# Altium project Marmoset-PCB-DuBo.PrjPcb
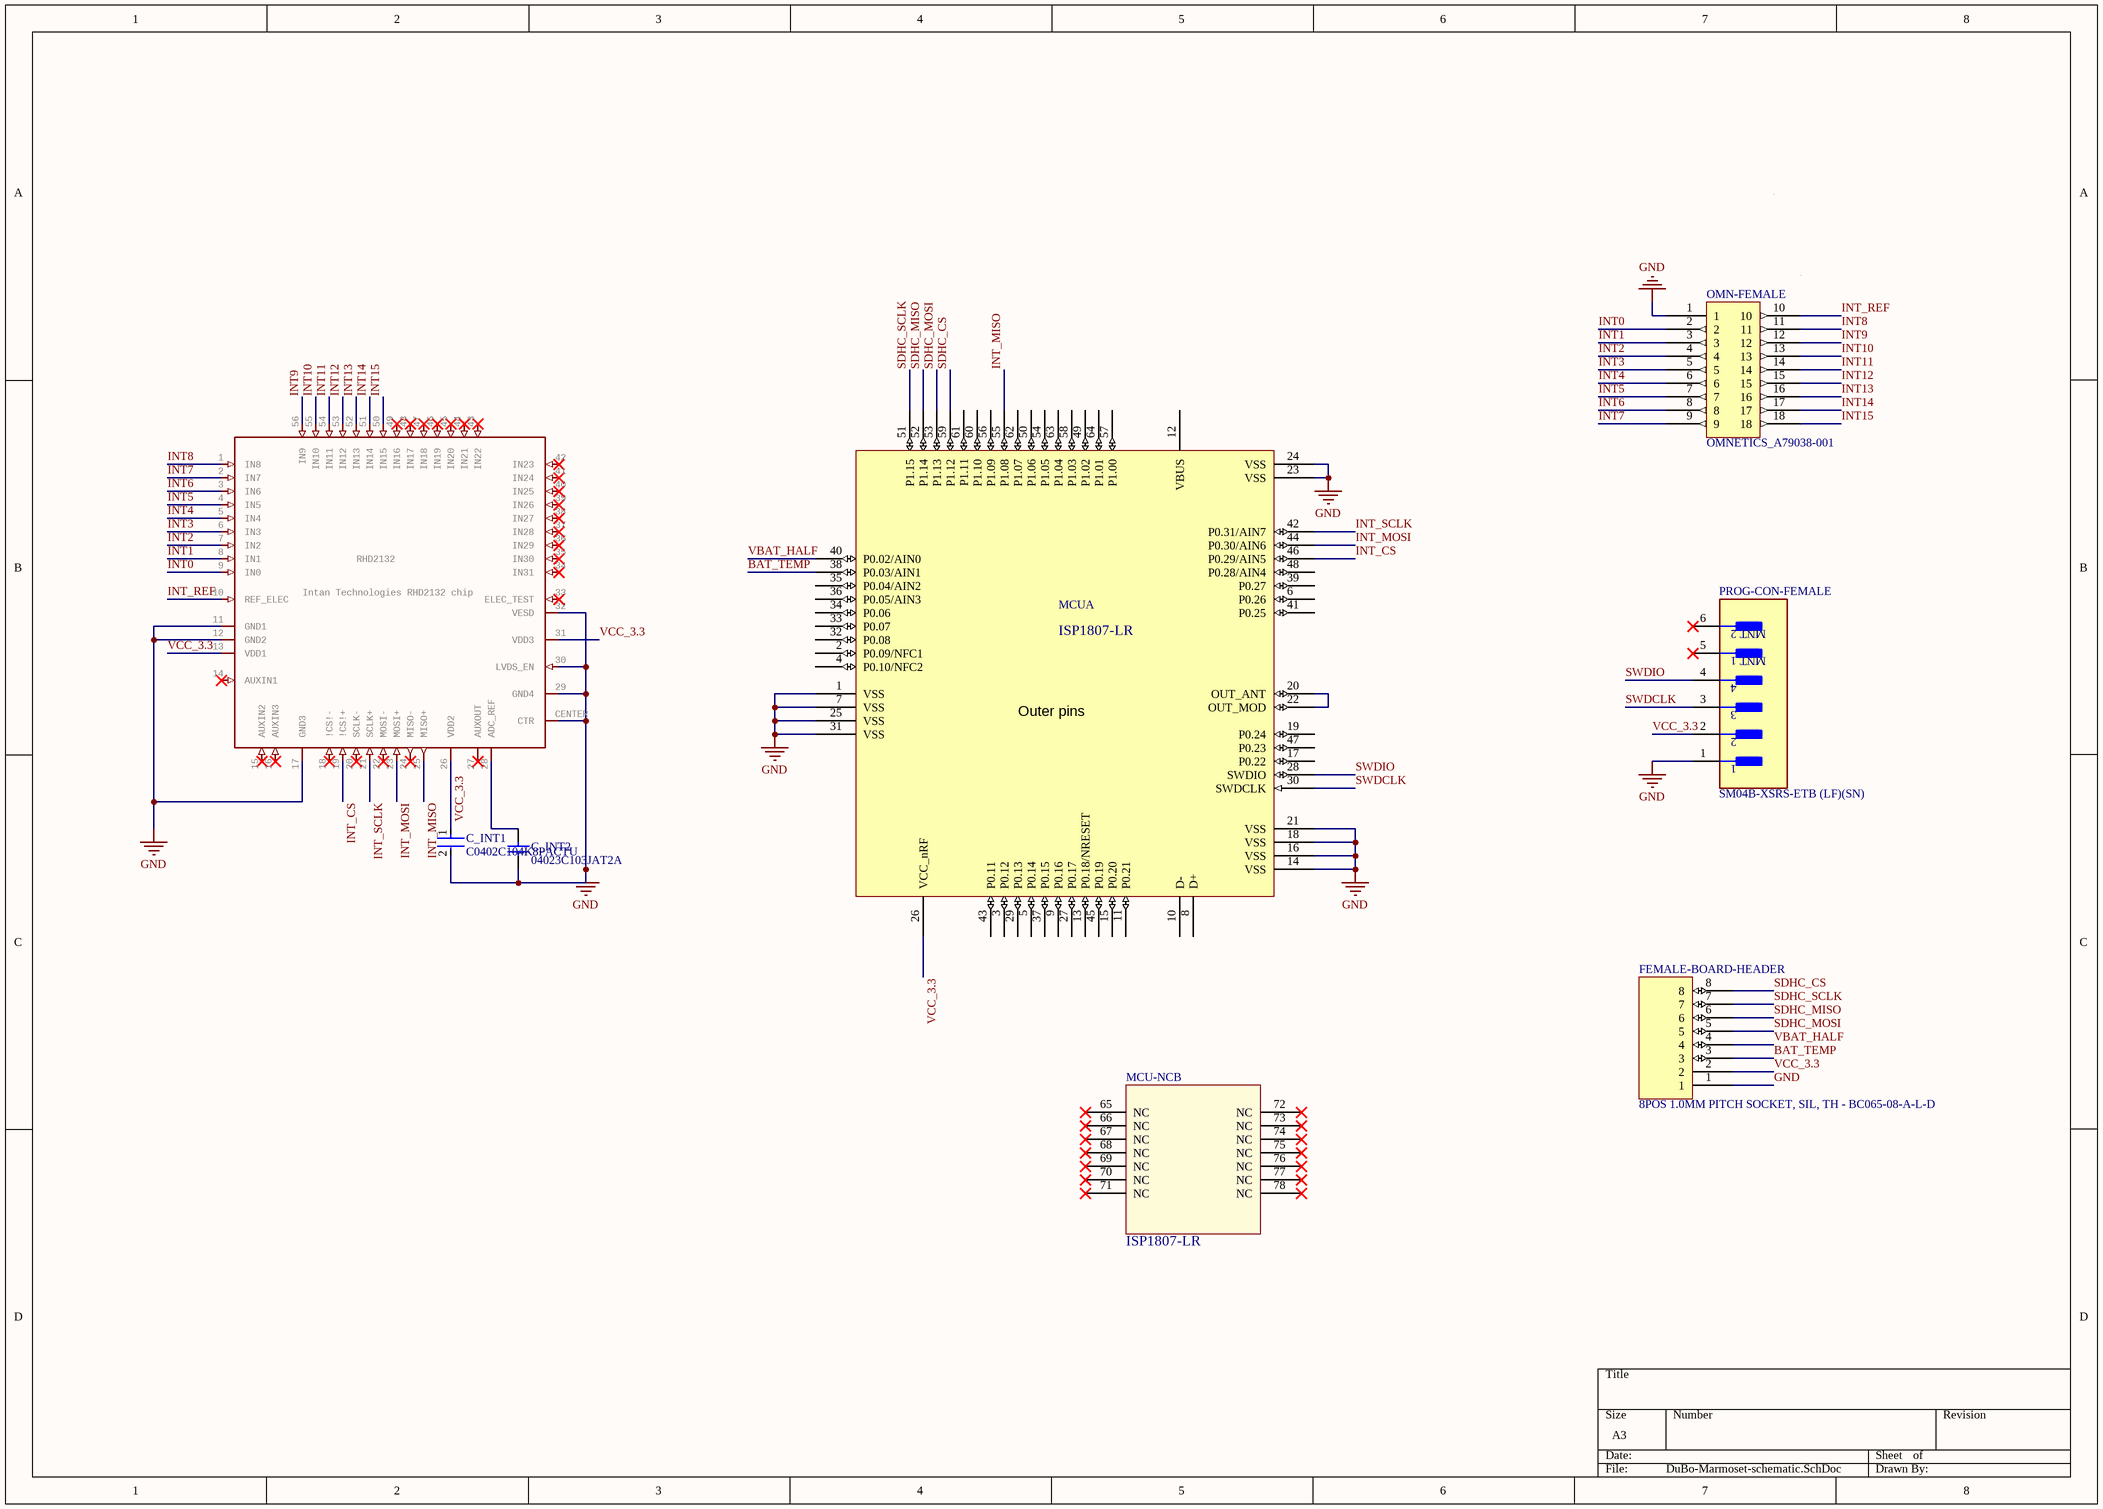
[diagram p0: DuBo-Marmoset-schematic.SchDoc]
1 sheet, 8 parts. Net scope: global (net labels, ports and power ports of the same name join across sheets).
Board file: DuBo-Marmoset-PCB1.PcbDoc

## Sheet DuBo-Marmoset-schematic.SchDoc
size A3; SheetNumber: 1; SheetTotal: 1

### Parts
C_INT1  C0402C104K8PACTU  [FP-C0402-BB-MFG]
C_INT2  04023C103JAT2A  [CAPC1005X56X25ML10T15]
FEMALE-BOARD-HEADER  8POS 1.0MM PITCH SOCKET, SIL, TH - BC065-08-A-L-D  [FEMALE-BOARD-HEADER-8]
MCU  ISP1807  [ISP1807-LR]  (value not drawn)  (part A of 2)
MCU-NC  ISP1807  [ISP1807-LR]  (value not drawn)  (part B of 2)
OMN-FEMALE  OMNETICS_A79038-001  [OMNETICS_A79038-001_Footprint]
PROG-CON-FEMALE  SM04B-XSRS-ETB (LF)(SN)  [FP-SM04B-XSRS-ETB_LF_SN-MFG]
RHD2132  Intan Technologies RHD2132 chip  [QFN56_8_X_8_LARGE]

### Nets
GND: C_INT1.2 C_INT2.2 FEMALE-BOARD-HEADER.1 MCU.1(VSS) MCU.7(VSS) MCU.14(VSS) MCU.16(VSS) MCU.18(VSS) MCU.21(VSS) MCU.23(VSS) MCU.24(VSS) MCU.25(VSS) MCU.31(VSS) OMN-FEMALE.1 PROG-CON-FEMALE.1 RHD2132.11(GND1) RHD2132.12(GND2) RHD2132.17(GND3) RHD2132.29(GND4) RHD2132.30(LVDS_EN) RHD2132.32(VESD) RHD2132.CENTER(CTR)
BAT_TEMP: FEMALE-BOARD-HEADER.3 MCU.38(P0.03/AIN1)
INT0: OMN-FEMALE.2 RHD2132.9(IN0)
INT1: OMN-FEMALE.3 RHD2132.8(IN1)
INT2: OMN-FEMALE.4 RHD2132.7(IN2)
INT3: OMN-FEMALE.5 RHD2132.6(IN3)
INT~{4}: OMN-FEMALE.6 RHD2132.5(IN4)
INT5: OMN-FEMALE.7 RHD2132.4(IN5)
INT6: OMN-FEMALE.8 RHD2132.3(IN6)
INT7: OMN-FEMALE.9 RHD2132.2(IN7)
INT8: OMN-FEMALE.11 RHD2132.1(IN8)
INT9: OMN-FEMALE.12 RHD2132.56(IN9)
INT10: OMN-FEMALE.13 RHD2132.55(IN10)
INT11: OMN-FEMALE.14 RHD2132.54(IN11)
INT12: OMN-FEMALE.15 RHD2132.53(IN12)
INT13: OMN-FEMALE.16 RHD2132.52(IN13)
INT14: OMN-FEMALE.17 RHD2132.51(IN14)
INT15: OMN-FEMALE.18 RHD2132.50(IN15)
INT_CS: MCU.46(P0.29/AIN5) RHD2132.19(!CS!+)
INT_MISO: MCU.55(P1.08) RHD2132.25(MISO+)
INT_MOSI: MCU.44(P0.30/AIN6) RHD2132.23(MOSI+)
INT_REF: OMN-FEMALE.10 RHD2132.10(REF_ELEC)
INT_SCLK: MCU.42(P0.31/AIN7) RHD2132.21(SCLK+)
SDHC_CS: FEMALE-BOARD-HEADER.8 MCU.59(P1.12)
SDHC_MISO: FEMALE-BOARD-HEADER.6 MCU.52(P1.14)
SDHC_MOSI: FEMALE-BOARD-HEADER.5 MCU.53(P1.13)
SDHC_SCLK: FEMALE-BOARD-HEADER.7 MCU.51(P1.15)
SWDCLK: MCU.30(SWDCLK) PROG-CON-FEMALE.3
SWDIO: MCU.28(SWDIO) PROG-CON-FEMALE.4
VBAT_HALF: FEMALE-BOARD-HEADER.4 MCU.40(P0.02/AIN0)
VCC_3.3: C_INT1.1 FEMALE-BOARD-HEADER.2 MCU.26(VCC_nRF) PROG-CON-FEMALE.2 RHD2132.13(VDD1) RHD2132.26(VDD2) RHD2132.31(VDD3)
NetC_INT2_1: C_INT2.1 RHD2132.28(ADC_REF)
NetMCU_20: MCU.20(OUT_ANT) MCU.22(OUT_MOD)

Not connected (* = marked no-connect by the designer): MCU 2(P0.09/NFC1) 3(P0.12) 4(P0.10/NFC2) 5(P0.14) 6(P0.26) 8(D+) 9(P0.16) 10(D-) 11(P0.21) 12(VBUS) 13(P0.18/NRESET) 15(P0.20) 17(P0.22) 19(P0.24) 27(P0.17) 29(P0.13) 32(P0.08) 33(P0.07) 34(P0.06) 35(P0.04/AIN2) 36(P0.05/AIN3) 37(P0.15) 39(P0.27) 41(P0.25) 43(P0.11) 45(P0.19) 47(P0.23) 48(P0.28/AIN4) 49(P1.02) 50(P1.06) 54(P1.05) 56(P1.09) 57(P1.00) 58(P1.03) 60(P1.10) 61(P1.11) 62(P1.07) 63(P1.04) 64(P1.01); MCU-NC 65(NC)* 66(NC)* 67(NC)* 68(NC)* 69(NC)* 70(NC)* 71(NC)* 72(NC)* 73(NC)* 74(NC)* 75(NC)* 76(NC)* 77(NC)* 78(NC)*; PROG-CON-FEMALE 5(MNT_1)* 6(MNT_2)*; RHD2132 14(AUXIN1)* 15(AUXIN2)* 16(AUXIN3)* 18(!CS!-)* 20(SCLK-)* 22(MOSI-)* 24(MISO-)* 27(AUXOUT)* 33(ELEC_TEST)* 34(IN31)* 35(IN30)* 36(IN29)* 37(IN28)* 38(IN27)* 39(IN26)* 40(IN25)* 41(IN24)* 42(IN23)* 43(IN22)* 44(IN21)* 45(IN20)* 46(IN19)* 47(IN18)* 48(IN17)* 49(IN16)*

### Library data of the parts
C_INT1 = CMP-2008-02046-2: CAP CER 0.1UF 10V X5R 0402; Manufacturer: Kemet; Capacitance: 0.10 μF; Temperature Coefficient: 15%; Tolerance: 0.1; Value: 0.10 μF
C_INT2 = CMP-2008-02925-1: Manufacturer: AVX Interconnect / Elco
FEMALE-BOARD-HEADER = FEMALE-BOARD-HEADER-8: System: Connector
MCU MCU-NC = ISP1807-LR: ISP Smart Bluetooth Module; BOI-Metric: QFN 8 x 8; DESIG: BLE Module; FAB: Insight SiP
OMN-FEMALE = OMNETICS_A79038-001: 18 PIN FEMALE NANO DUAL ROW CONNECTOR W/GUIDE POST HOLES
PROG-CON-FEMALE = CMP-17439-000402-2: CONN HEADER SMD R/A 4POS 0.6MM; Number of Contacts: 4; Voltage Rating: 30V; Current Rating: 200mA
RHD2132 = RHD2132_QFN: GateName_1: A; DeviceName: _QFN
